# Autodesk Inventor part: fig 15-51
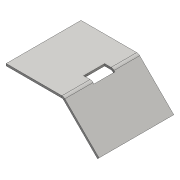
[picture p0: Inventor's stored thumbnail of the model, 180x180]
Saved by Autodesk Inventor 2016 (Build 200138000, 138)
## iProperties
Created: 2015-07
Part Number: fig 15-51
Material: Generic
Document SubType Name: Sheet Metal
Designer: Sandeep
Density: 1 g/cm^3
Sheet Metal Rule: Default_mm
Appearance: Default
Author: Sandeep
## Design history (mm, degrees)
node "Face1"
  sketch "Sketch1"
    geometry: L1 (-9.283, 8.313)-(4.503, 8.313); L2 (4.503, 8.313)-(4.503, -9.63); L3 (4.503, -9.63)-(-9.283, -9.63); L4 (-9.283, -9.63)-(-9.283, 8.313); 1 further point
    constraints: 8 end point, 2 parallel, 1 horizontal, 1 perpendicular
node "Flange1"
sketch "Sketch3"
  geometry: L1 (2.535, 2.162)-(6.789, 2.162); L2 (6.789, 2.162)-(6.789, -2.878); L3 (6.789, -2.878)-(2.535, -2.878); L4 (2.535, -2.878)-(2.535, 2.162); 1 further point
  constraints: 8 end point, 2 parallel, 1 horizontal, 1 perpendicular
cut "Cut1" sketch "Sketch3" dims "d11" = 0.5 (= Thickness), "d12" = 0
body "Solid1"
face "Plate1" dims "Thickness" = 0.5
sketch "Sketch2"
  geometry: L1 through (8.971, 0) direction (-1, 0); L2 through (0, -6) direction (0, -1); L3 (0, -12)-(17.943, -12); L4 (17.943, -12)-(17.943, 0)
  constraints: 6 end point, 1 horizontal, 1 perpendicular, 1 vertical
face "Plate2" dims "d1" = 0.5 (= BendReliefWidth), "d2" = 0.25 (= BendReliefDepth), "d3" = 1 (= MinimumRemnant), "d4" = 0.5 (= BendRadius), "d5" = 12, "d6" = 45 deg, "d7" = 0.5 (= BendRadius), "d8" = 2 (= CornerReliefSize), "d9" = 0.5 (= GapSize), "d10" = 0.5 (= JacobiRadiusSize), "SeamGap" = 0.01, "Thickness" = 0.5
bend "Bend1" dims "d1" = 0.5 (= BendReliefWidth), "d2" = 0.25 (= BendReliefDepth), "d3" = 1 (= MinimumRemnant), "d4" = 0.5 (= BendRadius), "d5" = 12, "d6" = 45 deg, "d7" = 0.5 (= BendRadius), "SeamGap" = 0.01, "Thickness" = 0.5
feature "Corner1" dims "d5" = 12, "d6" = 45 deg, "d8" = 2 (= CornerReliefSize), "d9" = 0.5 (= GapSize), "d10" = 0.5 (= JacobiRadiusSize)
other parameters: "BendRadius" = 0.5 (= Thickness), "BendReliefWidth" = 0.5 (= Thickness), "BendReliefDepth" = 0.25 (= 0.5 x Thickness), "CornerReliefSize" = 2 (= 4 x Thickness), "MinimumRemnant" = 1 (= 2 x Thickness), "TransitionRadius" = 0.5 (= BendRadius), "JacobiRadiusSize" = 0.5 (= BendRadius), "GapSize" = 0.5 (= Thickness), "d0" = 0.5 (= BendRadius)
